// Mitsubishi GX Works2 project: 3.单按钮控制   PLC: FX3U/FX3UC

PROGRAM MAIN
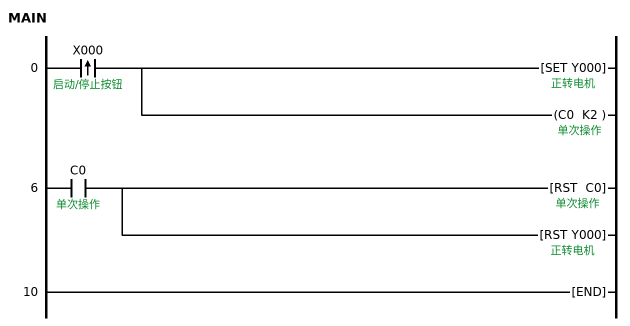
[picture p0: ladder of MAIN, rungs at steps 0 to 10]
0     LDP     X000  ; 启动/停止按钮
      SET     Y000  ; 正转电机
      OUT     C0 K2  ; 单次操作
6     LD      C0  ; 单次操作
      RST     C0  ; 单次操作
      RST     Y000  ; 正转电机
10    END
END_PROGRAM

// device comments not shown above
X001  ; 反转按钮
X002  ; 停止按钮
Y001  ; 反转电机
M0  ; 电机启动标志
